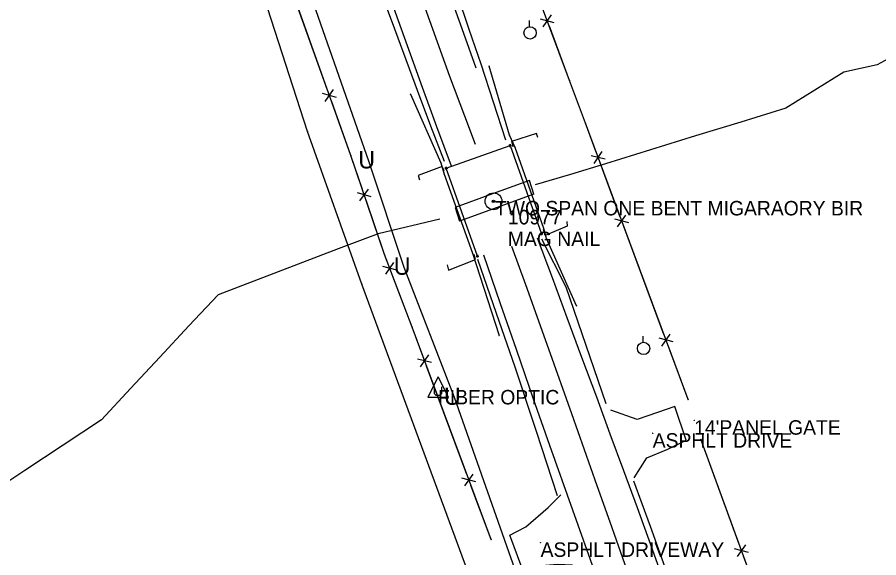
# Model space of a CAD drawing. Extents: x 1050807 to 1053552, y 395828 to 398415.
# Drawn here: x 1052207.8 to 1052505.9, y 396867.1 to 397054.1 of the extents above; entities that cross this region are included whole.
import ezdxf

# ---------------------------------------------------------------- set-up
doc = ezdxf.new("R2010")
doc.units = 0
for name, color, linetype in [('Default', 7, 'Continuous'), ('S_BRIDGE', 7, 'Continuous'), ('S_DITCHLINE', 7, 'Continuous'), ('S_DRIVEWAY', 7, 'Continuous'), ('S_EDGE_CONCRETE', 7, 'Continuous'), ('S_EDGE_PAVEMENT', 7, 'Continuous'), ('S_FENCE', 7, 'Continuous'), ('S_GUARDRAIL', 7, 'Continuous'), ('S_IRON_PIN', 7, 'Continuous'), ('S_IRON_PIN_ANNOT', 7, 'Continuous'), ('S_MSC_PT_SYM', 7, 'Continuous'), ('S_PAVEMENT_CROWN', 7, 'Continuous'), ('S_RDW_PT_SYM', 7, 'Continuous'), ('S_SHOULDER', 7, 'Continuous'), ('S_STR_PT_SYM', 7, 'Continuous'), ('S_SURVEY_TEXT_ANNOT', 7, 'Continuous'), ('S_UNDERGROUND_CABLE', 7, 'Continuous'), ('S_UTILITY_POLE', 7, 'Continuous'), ('S_UTILITY_POLE_ANNOT', 7, 'Continuous'), ('S_UTL_PT_SYM', 7, 'Continuous'), ('S_WATER_UTILITIES', 7, 'Continuous')]:
    doc.layers.add(name, color=color, linetype=linetype)

msp = doc.modelspace()

# ---------------------------------------------------------------- linework, layer by layer
at = {"layer": 'Default'}
msp.add_line((1052386.58, 396992.91), (1052360.83, 396983.6), dxfattribs=at)
at = {"layer": 'S_BRIDGE'}
for p, q in [((1052356.26, 397001.86), (1052378.36, 397009.7)), ((1052378.36, 397009.7), (1052389.23, 396979.16)), ((1052367.08, 396971.45), (1052356.26, 397001.86))]:
    msp.add_line(p, q, dxfattribs=at)
at = {"layer": 'S_DITCHLINE'}
for points in [[(1052527.01, 397049.39), (1052505.34, 397037.66), (1052493.8, 397035.07), (1052473.74, 397022.69), (1052458.15, 397017.87), (1052442.57, 397013.04), (1052426.98, 397008.21), (1052411.4, 397003.39), (1052399.23, 396999.74), (1052387.06, 396996.09)], [(1052354.06, 396984.29), (1052332.65, 396979.22), (1052318.8, 396973.94), (1052304.96, 396968.66), (1052291.11, 396963.39), (1052277.27, 396958.11), (1052267.19, 396947.28), (1052257.11, 396936.44), (1052247.03, 396925.61), (1052236.94, 396914.77), (1052223.68, 396906.01), (1052210.41, 396897.26), (1052197.14, 396888.5)]]:
    msp.add_lwpolyline(points, dxfattribs=at)
at = {"layer": 'S_DRIVEWAY'}
for points in [[(1052421.27, 396894.68), (1052425.64, 396901.61), (1052432.9, 396904.62), (1052439.32, 396907.78), (1052435.42, 396919.44), (1052429.36, 396917.37), (1052422.3, 396914.94), (1052413.21, 396918.18)], [(1052406.35, 396861.47), (1052399.84, 396864.53), (1052394.81, 396864.76), (1052382.42, 396863.64), (1052378.24, 396874.85), (1052383.77, 396877.82), (1052391.56, 396884.45), (1052395.94, 396888.79)]]:
    msp.add_lwpolyline(points, dxfattribs=at)
at = {"layer": 'S_EDGE_CONCRETE'}
for points in [[(1052387.95, 397012.47), (1052387.46, 397013.92), (1052378.82, 397011.09), (1052379.27, 397009.34)], [(1052355.51, 397000.96), (1052354.8, 397002.42), (1052346.54, 396999.36), (1052346.97, 396997.9)], [(1052386.58, 396992.91), (1052385.07, 396997.59), (1052372.23, 396992.96), (1052359.38, 396988.33), (1052360.83, 396983.6)], [(1052397.96, 396983.42), (1052398.14, 396981.83), (1052390.5, 396978.57), (1052389.87, 396980.65)], [(1052356.57, 396968.43), (1052356.98, 396966.58), (1052366.43, 396970.3), (1052365.89, 396972.03)]]:
    msp.add_lwpolyline(points, dxfattribs=at)
at = {"layer": 'S_EDGE_PAVEMENT'}
for points in [[(1052366.56, 397036.55), (1052362.3, 397048.53), (1052358.05, 397060.51), (1052353.79, 397072.49), (1052349.54, 397084.47), (1052341.79, 397106.52), (1052334.05, 397128.57), (1052326.07, 397151.2), (1052318.09, 397173.83), (1052310.11, 397196.56), (1052302.13, 397219.28), (1052294.23, 397241.56), (1052286.33, 397263.84), (1052278.39, 397285.89), (1052270.44, 397307.95), (1052265.77, 397320.81), (1052261.1, 397333.67), (1052256.44, 397346.52), (1052251.77, 397359.38), (1052244.05, 397379.98), (1052236.34, 397400.57)], [(1052358.04, 397002.59), (1052353.03, 397016.23), (1052348.02, 397029.87), (1052339.76, 397052.84), (1052331.5, 397075.82), (1052327.24, 397087.68), (1052322.99, 397099.53), (1052318.74, 397111.39), (1052314.49, 397123.25), (1052310.27, 397135.03), (1052306.04, 397146.82), (1052301.81, 397158.61), (1052297.59, 397170.39), (1052289.45, 397193.11), (1052281.31, 397215.83), (1052273.5, 397237.65), (1052265.69, 397259.46), (1052257.46, 397282.59), (1052249.24, 397305.71), (1052241.37, 397327.67), (1052233.5, 397349.63), (1052225.59, 397371.79), (1052217.68, 397393.96)], [(1052460.97, 396776.43), (1052456.62, 396788.55), (1052452.28, 396800.67), (1052447.93, 396812.79), (1052443.59, 396824.9), (1052435.34, 396848.24), (1052427.09, 396871.57), (1052422.4, 396884.33), (1052417.71, 396897.09), (1052413.02, 396909.86), (1052408.33, 396922.62), (1052403.21, 396936.38), (1052398.09, 396950.14), (1052392.97, 396963.89), (1052387.86, 396977.65)], [(1052440.47, 396769.17), (1052432.33, 396792.24), (1052424.18, 396815.32), (1052416.08, 396838.25), (1052407.97, 396861.18), (1052400.04, 396883.52), (1052392.11, 396905.86), (1052386.39, 396922.34), (1052380.67, 396938.83), (1052374.95, 396955.32), (1052369.23, 396971.8)]]:
    msp.add_lwpolyline(points, dxfattribs=at)
at = {"layer": 'S_FENCE'}
for p, q in [((1052323.23, 397006.32), (1052293.27, 397090.24)), ((1052398.87, 397032.26), (1052380.46, 397081.99)), ((1052393.65, 397052.25), (1052388.82, 397053.52)), ((1052393.65, 397052.25), (1052388.82, 397053.52)), ((1052389.81, 397050.83), (1052392.66, 397054.94)), ((1052389.81, 397050.83), (1052392.66, 397054.94)), ((1052404.42, 397017.45), (1052398.87, 397032.26)), ((1052318.25, 397026.38), (1052313.43, 397027.71)), ((1052318.25, 397026.38), (1052313.43, 397027.71)), ((1052314.39, 397025), (1052317.28, 397029.08)), ((1052314.39, 397025), (1052317.28, 397029.08)), ((1052439.97, 396921.79), (1052404.42, 397017.45)), ((1052334.91, 396972), (1052323.23, 397006.32)), ((1052411.25, 397004.96), (1052406.41, 397006.22)), ((1052411.25, 397004.96), (1052406.41, 397006.22)), ((1052407.41, 397003.53), (1052410.25, 397007.65)), ((1052407.41, 397003.53), (1052410.25, 397007.65)), ((1052326.4, 396990.64), (1052329.37, 396994.66)), ((1052326.4, 396990.64), (1052329.37, 396994.66)), ((1052330.28, 396991.96), (1052325.49, 396993.34)), ((1052330.28, 396991.96), (1052325.49, 396993.34)), ((1052415.57, 396981.57), (1052418.41, 396985.69)), ((1052415.57, 396981.57), (1052418.41, 396985.69)), ((1052419.41, 396983), (1052414.57, 396984.26)), ((1052419.41, 396983), (1052414.57, 396984.26)), ((1052344.42, 396946.89), (1052334.91, 396972)), ((1052339.14, 396966.62), (1052334.3, 396967.82)), ((1052339.14, 396966.62), (1052334.3, 396967.82)), ((1052335.31, 396965.17), (1052338.13, 396969.27)), ((1052335.31, 396965.17), (1052338.13, 396969.27)), ((1052371.77, 396873.36), (1052344.42, 396946.89)), ((1052434.73, 396941.78), (1052429.89, 396943.04)), ((1052434.73, 396941.78), (1052429.89, 396943.04)), ((1052430.89, 396940.35), (1052433.73, 396944.46)), ((1052430.89, 396940.35), (1052433.73, 396944.46)), ((1052347.34, 396933.16), (1052350.18, 396937.28)), ((1052347.34, 396933.16), (1052350.18, 396937.28)), ((1052351.18, 396934.59), (1052346.34, 396935.85)), ((1052351.18, 396934.59), (1052346.34, 396935.85)), ((1052466.02, 396848.87), (1052444.41, 396908.05)), ((1052362.68, 396891.92), (1052365.52, 396896.04)), ((1052362.68, 396891.92), (1052365.52, 396896.04)), ((1052366.52, 396893.35), (1052361.68, 396894.61)), ((1052366.52, 396893.35), (1052361.68, 396894.61)), ((1052457.05, 396867.46), (1052459.92, 396871.56)), ((1052457.05, 396867.46), (1052459.92, 396871.56)), ((1052460.9, 396868.87), (1052456.07, 396870.15)), ((1052460.9, 396868.87), (1052456.07, 396870.15))]:
    msp.add_line(p, q, dxfattribs=at)
for points in [[(1052315.16, 397028.93), (1052301.71, 397066.6)], [(1052315.16, 397028.93), (1052301.71, 397066.6)], [(1052398.87, 397032.26), (1052391.93, 397051.01)], [(1052398.87, 397032.26), (1052391.93, 397051.01)], [(1052404.42, 397017.45), (1052398.87, 397032.26)], [(1052404.42, 397017.45), (1052398.87, 397032.26)], [(1052323.23, 397006.32), (1052316.51, 397025.16)], [(1052323.23, 397006.32), (1052316.51, 397025.16)], [(1052408.13, 397007.46), (1052404.42, 397017.45)], [(1052408.13, 397007.46), (1052404.42, 397017.45)], [(1052327.25, 396994.53), (1052323.23, 397006.32)], [(1052327.25, 396994.53), (1052323.23, 397006.32)], [(1052416.49, 396984.98), (1052409.52, 397003.71)], [(1052416.49, 396984.98), (1052409.52, 397003.71)], [(1052334.91, 396972), (1052328.52, 396990.77)], [(1052334.91, 396972), (1052328.52, 396990.77)], [(1052431.61, 396944.28), (1052417.68, 396981.76)], [(1052431.61, 396944.28), (1052417.68, 396981.76)], [(1052336.02, 396969.07), (1052334.91, 396972)], [(1052336.02, 396969.07), (1052334.91, 396972)], [(1052344.42, 396946.89), (1052337.42, 396965.37)], [(1052344.42, 396946.89), (1052337.42, 396965.37)], [(1052348.26, 396936.57), (1052344.42, 396946.89)], [(1052348.26, 396936.57), (1052344.42, 396946.89)], [(1052439.97, 396921.79), (1052433.01, 396940.53)], [(1052439.97, 396921.79), (1052433.01, 396940.53)], [(1052363.4, 396895.86), (1052349.46, 396933.35)], [(1052363.4, 396895.86), (1052349.46, 396933.35)], [(1052457.8, 396871.38), (1052444.41, 396908.05)], [(1052457.8, 396871.38), (1052444.41, 396908.05)], [(1052371.77, 396873.36), (1052364.79, 396892.11)], [(1052371.77, 396873.36), (1052364.79, 396892.11)], [(1052466.02, 396848.87), (1052459.17, 396867.63)], [(1052466.02, 396848.87), (1052459.17, 396867.63)]]:
    msp.add_lwpolyline(points, dxfattribs=at)
at = {"layer": 'S_GUARDRAIL'}
for p, q in [((1052378.14, 397013.36), (1052371.06, 397037.17)), ((1052343.85, 397027.48), (1052354.43, 397003.78)), ((1052380.16, 397009.02), (1052378.14, 397013.36)), ((1052390.06, 396981.02), (1052380.16, 397009.02)), ((1052354.43, 397003.78), (1052355.5, 396999.84)), ((1052355.5, 396999.84), (1052365.3, 396972.53)), ((1052390.93, 396977.52), (1052390.06, 396981.02)), ((1052401.34, 396954.31), (1052390.93, 396977.52)), ((1052365.3, 396972.53), (1052366.57, 396968.56)), ((1052366.57, 396968.56), (1052374.55, 396944.03))]:
    msp.add_line(p, q, dxfattribs=at)
at = {"layer": 'S_IRON_PIN'}
for radius in [2.91, 0.411, 0.262, 0.212, 0.145, 0.0822, 0.0581]:
    msp.add_circle((1052372.59, 396990.44), radius, dxfattribs=at)
at = {"layer": 'S_MSC_PT_SYM'}
for points in [[(1052398.87, 397032.26), (1052398.87, 397032.31), (1052398.87, 397032.26), (1052398.82, 397032.26), (1052398.87, 397032.26), (1052398.87, 397032.21), (1052398.87, 397032.26), (1052398.92, 397032.26)], [(1052404.42, 397017.45), (1052404.42, 397017.5), (1052404.42, 397017.45), (1052404.37, 397017.45), (1052404.42, 397017.45), (1052404.42, 397017.4), (1052404.42, 397017.45), (1052404.47, 397017.45)], [(1052323.23, 397006.32), (1052323.23, 397006.37), (1052323.23, 397006.32), (1052323.18, 397006.32), (1052323.23, 397006.32), (1052323.23, 397006.27), (1052323.23, 397006.32), (1052323.28, 397006.32)], [(1052373.12, 396990.55), (1052373.12, 396990.6), (1052373.12, 396990.55), (1052373.07, 396990.55), (1052373.12, 396990.55), (1052373.12, 396990.5), (1052373.12, 396990.55), (1052373.17, 396990.55)], [(1052334.91, 396972), (1052334.91, 396972.05), (1052334.91, 396972), (1052334.86, 396972), (1052334.91, 396972), (1052334.91, 396971.95), (1052334.91, 396972), (1052334.96, 396972)], [(1052344.42, 396946.89), (1052344.42, 396946.94), (1052344.42, 396946.89), (1052344.37, 396946.89), (1052344.42, 396946.89), (1052344.42, 396946.84), (1052344.42, 396946.89), (1052344.47, 396946.89)], [(1052439.97, 396921.79), (1052439.97, 396921.84), (1052439.97, 396921.79), (1052439.92, 396921.79), (1052439.97, 396921.79), (1052439.97, 396921.74), (1052439.97, 396921.79), (1052440.02, 396921.79)], [(1052442.07, 396914.66), (1052442.07, 396914.71), (1052442.07, 396914.66), (1052442.02, 396914.66), (1052442.07, 396914.66), (1052442.07, 396914.61), (1052442.07, 396914.66), (1052442.12, 396914.66)], [(1052427.71, 396910.17), (1052427.71, 396910.22), (1052427.71, 396910.17), (1052427.66, 396910.17), (1052427.71, 396910.17), (1052427.71, 396910.12), (1052427.71, 396910.17), (1052427.76, 396910.17)], [(1052444.41, 396908.05), (1052444.41, 396908.1), (1052444.41, 396908.05), (1052444.36, 396908.05), (1052444.41, 396908.05), (1052444.41, 396908.01), (1052444.41, 396908.05), (1052444.46, 396908.05)], [(1052371.77, 396873.36), (1052371.77, 396873.41), (1052371.77, 396873.36), (1052371.72, 396873.36), (1052371.77, 396873.36), (1052371.77, 396873.31), (1052371.77, 396873.36), (1052371.82, 396873.36)], [(1052388.91, 396872.37), (1052388.91, 396872.42), (1052388.91, 396872.37), (1052388.86, 396872.37), (1052388.91, 396872.37), (1052388.91, 396872.32), (1052388.91, 396872.37), (1052388.96, 396872.37)]]:
    msp.add_lwpolyline(points, dxfattribs=at)
at = {"layer": 'S_PAVEMENT_CROWN'}
for points in [[(1052366.34, 397010.04), (1052362.68, 397019.85), (1052357.54, 397033.59), (1052353.25, 397045.49), (1052348.97, 397057.39), (1052344.68, 397069.29), (1052340.39, 397081.19), (1052336.12, 397093.01), (1052331.85, 397104.83), (1052327.58, 397116.64), (1052323.31, 397128.46), (1052314.8, 397151.75), (1052306.28, 397175.04), (1052298.35, 397197.17), (1052290.41, 397219.3)], [(1052450.54, 396775.06), (1052442.17, 396797.78), (1052433.8, 396820.49), (1052425.59, 396843.69), (1052417.38, 396866.9), (1052412.95, 396879.4), (1052408.53, 396891.91), (1052404.1, 396904.42), (1052399.68, 396916.93), (1052391.71, 396939.22), (1052383.74, 396961.52), (1052378.98, 396974.84)]]:
    msp.add_lwpolyline(points, dxfattribs=at)
at = {"layer": 'S_RDW_PT_SYM'}
for points in [[(1052371.06, 397037.17), (1052371.06, 397037.22), (1052371.06, 397037.17), (1052371.01, 397037.17), (1052371.06, 397037.17), (1052371.06, 397037.12), (1052371.06, 397037.17), (1052371.11, 397037.17)], [(1052343.85, 397027.48), (1052343.85, 397027.53), (1052343.85, 397027.48), (1052343.8, 397027.48), (1052343.85, 397027.48), (1052343.85, 397027.43), (1052343.85, 397027.48), (1052343.91, 397027.48)], [(1052378.14, 397013.36), (1052378.14, 397013.41), (1052378.14, 397013.36), (1052378.09, 397013.36), (1052378.14, 397013.36), (1052378.14, 397013.31), (1052378.14, 397013.36), (1052378.19, 397013.36)], [(1052380.16, 397009.02), (1052380.16, 397009.07), (1052380.16, 397009.02), (1052380.11, 397009.02), (1052380.16, 397009.02), (1052380.16, 397008.97), (1052380.16, 397009.02), (1052380.21, 397009.02)], [(1052354.43, 397003.78), (1052354.43, 397003.83), (1052354.43, 397003.78), (1052354.38, 397003.78), (1052354.43, 397003.78), (1052354.43, 397003.73), (1052354.43, 397003.78), (1052354.48, 397003.78)], [(1052355.5, 396999.84), (1052355.5, 396999.89), (1052355.5, 396999.84), (1052355.45, 396999.84), (1052355.5, 396999.84), (1052355.5, 396999.79), (1052355.5, 396999.84), (1052355.55, 396999.84)], [(1052390.06, 396981.02), (1052390.06, 396981.07), (1052390.06, 396981.02), (1052390.01, 396981.02), (1052390.06, 396981.02), (1052390.06, 396980.97), (1052390.06, 396981.02), (1052390.11, 396981.02)], [(1052390.93, 396977.52), (1052390.93, 396977.57), (1052390.93, 396977.52), (1052390.88, 396977.52), (1052390.93, 396977.52), (1052390.93, 396977.47), (1052390.93, 396977.52), (1052390.98, 396977.52)], [(1052365.3, 396972.53), (1052365.3, 396972.58), (1052365.3, 396972.53), (1052365.25, 396972.53), (1052365.3, 396972.53), (1052365.3, 396972.48), (1052365.3, 396972.53), (1052365.35, 396972.53)], [(1052366.57, 396968.56), (1052366.57, 396968.61), (1052366.57, 396968.56), (1052366.52, 396968.56), (1052366.57, 396968.56), (1052366.57, 396968.51), (1052366.57, 396968.56), (1052366.62, 396968.56)], [(1052401.34, 396954.31), (1052401.34, 396954.36), (1052401.34, 396954.31), (1052401.29, 396954.31), (1052401.34, 396954.31), (1052401.34, 396954.26), (1052401.34, 396954.31), (1052401.39, 396954.31)], [(1052374.55, 396944.03), (1052374.55, 396944.08), (1052374.55, 396944.03), (1052374.5, 396944.03), (1052374.55, 396944.03), (1052374.55, 396943.98), (1052374.55, 396944.03), (1052374.6, 396944.03)]]:
    msp.add_lwpolyline(points, dxfattribs=at)
at = {"layer": 'S_SHOULDER'}
for points in [[(1052355.65, 397004.17), (1052350.97, 397016.49), (1052346.3, 397028.81), (1052337.6, 397052.24), (1052328.9, 397075.66), (1052324.34, 397088.12), (1052319.79, 397100.59), (1052315.23, 397113.05), (1052310.67, 397125.51), (1052302.75, 397147.54), (1052294.83, 397169.57), (1052290.39, 397181.87), (1052285.96, 397194.16), (1052281.52, 397206.46), (1052277.09, 397218.75)], [(1052376.91, 397011.59), (1052372.6, 397024.74), (1052368.29, 397037.89), (1052364.22, 397049.94), (1052360.16, 397061.99), (1052356.09, 397074.04), (1052352.02, 397086.1), (1052347.33, 397099.36), (1052342.65, 397112.63), (1052337.97, 397125.9), (1052333.29, 397139.16), (1052326.21, 397158.59), (1052319.13, 397178.02)], [(1052411.59, 396920.33), (1052404.67, 396940.52), (1052397.75, 396960.7), (1052389.38, 396977.35)], [(1052394.79, 396888.47), (1052387.46, 396910.73), (1052380.13, 396932.99), (1052373.69, 396951.63), (1052367.24, 396970.26)], [(1052460.83, 396779.67), (1052455.93, 396795.51), (1052451.02, 396811.34), (1052446.43, 396824.04), (1052441.84, 396836.73), (1052437.25, 396849.42), (1052432.65, 396862.11), (1052426.93, 396877.84), (1052421.22, 396893.57)]]:
    msp.add_lwpolyline(points, dxfattribs=at)
at = {"layer": 'S_STR_PT_SYM'}
for points in [[(1052378.36, 397009.7), (1052378.36, 397010.2), (1052378.36, 397009.7), (1052377.86, 397009.7), (1052378.36, 397009.7), (1052378.36, 397009.2), (1052378.36, 397009.7), (1052378.86, 397009.7)], [(1052356.26, 397001.86), (1052356.26, 397002.36), (1052356.26, 397001.86), (1052355.76, 397001.86), (1052356.26, 397001.86), (1052356.26, 397001.36), (1052356.26, 397001.86), (1052356.76, 397001.86)], [(1052389.23, 396979.16), (1052389.23, 396979.66), (1052389.23, 396979.16), (1052388.73, 396979.16), (1052389.23, 396979.16), (1052389.23, 396978.66), (1052389.23, 396979.16), (1052389.73, 396979.16)], [(1052367.08, 396971.45), (1052367.08, 396971.95), (1052367.08, 396971.45), (1052366.58, 396971.45), (1052367.08, 396971.45), (1052367.08, 396970.95), (1052367.08, 396971.45), (1052367.58, 396971.45)]]:
    msp.add_lwpolyline(points, dxfattribs=at)
at = {"layer": 'S_UNDERGROUND_CABLE'}
for p, q in [((1052329.44, 397004.35), (1052302.83, 397080.43)), ((1052341.71, 396967.54), (1052329.44, 397004.35)), ((1052359.09, 396922.53), (1052341.71, 396967.54)), ((1052353.4, 396929.68), (1052349.87, 396922.59)), ((1052353.4, 396929.68), (1052356.88, 396922.59)), ((1052352.2, 396923.83), (1052352.2, 396926.27)), ((1052354.56, 396926.27), (1052354.56, 396923.83)), ((1052349.87, 396922.59), (1052356.88, 396922.59)), ((1052352.82, 396923.17), (1052352.2, 396923.83)), ((1052354.02, 396923.17), (1052352.82, 396923.17)), ((1052354.56, 396923.83), (1052354.02, 396923.17)), ((1052380.74, 396860.92), (1052359.09, 396922.53))]:
    msp.add_line(p, q, dxfattribs=at)
at = {"layer": 'S_UTILITY_POLE'}
for p, q in [((1052385.12, 397050.86), (1052385.12, 397052.97)), ((1052424.45, 396941.67), (1052424.45, 396943.78))]:
    msp.add_line(p, q, dxfattribs=at)
for centre in [(1052385.24, 397048.72), (1052424.57, 396939.53)]:
    msp.add_circle(centre, 2.13, dxfattribs=at)
at = {"layer": 'S_UTL_PT_SYM'}
for points in [[(1052308.23, 397014.61), (1052308.23, 397014.66), (1052308.23, 397014.61), (1052308.18, 397014.61), (1052308.23, 397014.61), (1052308.23, 397014.56), (1052308.23, 397014.61), (1052308.28, 397014.61)], [(1052327.05, 396961.77), (1052327.05, 396961.82), (1052327.05, 396961.77), (1052327, 396961.77), (1052327.05, 396961.77), (1052327.05, 396961.72), (1052327.05, 396961.77), (1052327.1, 396961.77)], [(1052334.35, 396941.99), (1052334.35, 396942.04), (1052334.35, 396941.99), (1052334.3, 396941.99), (1052334.35, 396941.99), (1052334.35, 396941.94), (1052334.35, 396941.99), (1052334.4, 396941.99)]]:
    msp.add_lwpolyline(points, dxfattribs=at)
at = {"layer": 'S_WATER_UTILITIES'}
for p, q in [((1052308.23, 397014.61), (1052280.47, 397100.74)), ((1052327.05, 396961.77), (1052308.23, 397014.61)), ((1052334.35, 396941.99), (1052327.05, 396961.77)), ((1052365.48, 396857.64), (1052334.35, 396941.99))]:
    msp.add_line(p, q, dxfattribs=at)

# ---------------------------------------------------------------- texts
at = {"layer": 'Default'}
for p in [(1052325.81, 397001.8), (1052338.08, 396965), (1052355.46, 396919.98)]:
    msp.add_text('U', height=6, dxfattribs=at).set_placement(p)
at = {"layer": 'S_IRON_PIN_ANNOT'}
for s, p in [('10977', (1052377.59, 396982.44)), ('MAG NAIL', (1052377.59, 396974.94))]:
    msp.add_text(s, height=5, dxfattribs=at).set_placement(p)
at = {"layer": 'S_SURVEY_TEXT_ANNOT'}
for s, p in [('TWO SPAN ONE BENT MIGARAORY BIR', (1052373.12, 396985.55)), ("14'PANEL GATE", (1052442.07, 396909.66)), ('ASPHLT DRIVE', (1052427.71, 396905.17)), ('ASPHLT DRIVEWAY', (1052388.91, 396867.37))]:
    msp.add_text(s, height=5, dxfattribs=at).set_placement(p)
at = {"layer": 'S_UTILITY_POLE_ANNOT'}
msp.add_text('FIBER OPTIC', height=5, dxfattribs=at).set_placement((1052353.4, 396920.14))

doc.saveas('drawing.dxf')
